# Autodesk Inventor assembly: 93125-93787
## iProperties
Author: Administrator
Shininess: 64.0
Angle Display Precision: 2
Document Length Units: 11272
Document Angle Units: 11286
Document Time Units: 11279
Document Mass Units: 11290
Document Length Units Precision: 3
Document Angle Units Precision: 2
Compacted: True
PropertySet Name: _Private Model Information
Created: 2002-03
Part Number: 93125-93787
Document SubType Name: Assembly
Designer: Administrator
Control State: 0
Master: False
Checked Out: False
PropertySet Name: Design Tracking Control
Density: 0.0
Volumn: 0.0
Area: 0.0
PropertySet Name: Model Information
